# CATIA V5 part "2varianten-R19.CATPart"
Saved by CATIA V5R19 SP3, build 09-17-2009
Part number: Part28
Bounding box of the stored display mesh (mm): x 0 to 2723.549, y 0 to 1294.795, z 0 to 553.46
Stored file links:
  C:\tmp\2varianten.CATPart
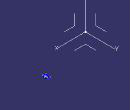
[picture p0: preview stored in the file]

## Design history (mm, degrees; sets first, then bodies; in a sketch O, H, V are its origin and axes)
AxisSystem1: origin (0, 0, 0), X (1, 0, 0), Y (0, 1, 0), Z (0, 0, 1)
Body1 (main body)
  Sketch1, origin (2734.4146, 556.3304, -287.4003), H (-0.1994, 0.9799, 0), V (0.1004, 0.0204, 0.9947)
    line L1 (542.1929, 772.1925) -> (586.583, 817.0912)
    line L2 (648.2969, 824.5497) -> (717.3635, 782.1525)
    line L3 (721.952, 751.9376) -> (684.9765, 709.68)
    line L4 (651.252, 696.1845) -> (591.7692, 701.592)
    line L5 (564.1559, 716.4399) -> (540.798, 745.6372)
    arc A1 centre (622.1392, 781.9379) radius 50 from (586.583, 817.0912) to (648.2969, 824.5497) cw
    arc A2 centre (706.9004, 765.1077) radius 20 from (717.3635, 782.1525) to (721.952, 751.9376) cw
    arc A3 centre (654.8735, 736.0202) radius 40 from (684.9765, 709.68) to (651.252, 696.1845) cw
    arc A4 centre (595.3906, 741.4277) radius 40 from (591.7692, 701.592) to (564.1559, 716.4399) cw
    arc A5 centre (556.4154, 758.1311) radius 20 from (540.798, 745.6372) to (542.1929, 772.1925) cw
    point P16 (737.5482, 769.7619)
    point P17 (671.5531, 694.3389)
    point P18 (614.4804, 845.3083)
    point P19 (529.6794, 759.5355)
    point P20 (574.8001, 703.1347)
    line L6 (737.5482, 769.7619) -> (614.4804, 845.3083)
    line L7 (614.4804, 845.3083) -> (529.6794, 759.5355)
    point P21 (529.6794, 759.5355)
    line L8 (529.6794, 759.5355) -> (574.8001, 703.1347)
    point P22 (671.5531, 694.3389)
    line L9 (671.5531, 694.3389) -> (737.5482, 769.7619)
    line L10 (671.5531, 694.3389) -> (574.8001, 703.1347)
    curve C1
    radius A1 = 50
    radius A2 = 20
    radius A3 = 40
    radius A4 = 40
    radius A5 = 20
    tangency: A1 L1, A1 L2, A2 L2, A2 L3, A3 L3, A3 L4, A4 L4, A4 L5, A5 L5, A5 L1, L6 A1, L8 A4, L9 A2, L10 A3
    coincidence: P16 L3, P16 L2, P17 L4, P17 L3, P18 L2, P18 L1, P19 L5, P19 L1, P20 L5, P20 L4, P21 L5, P21 L1, P22 L3
  Pad1: profile Sketch1, direction (0.9748, 0.1983, -0.1025), length 20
